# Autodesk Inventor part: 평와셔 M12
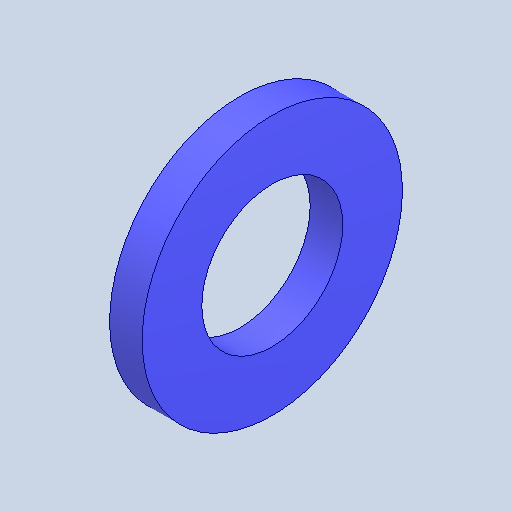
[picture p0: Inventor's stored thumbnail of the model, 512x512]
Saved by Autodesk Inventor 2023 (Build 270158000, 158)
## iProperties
Created: 2025-03
Part Number: 평와셔 M12
Material: 스테인리스강
Description: 평면 와셔
Document SubType Name: Modeling
Designer: user
Density: 8.08 g/cm^3
Appearance: 기본값
Author: jhkim
Sending System: Autodesk Inventor 2025
Preprocessor: ST-DEVELOPER v20
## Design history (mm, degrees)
feature "Solid1"
node "솔리드1"
